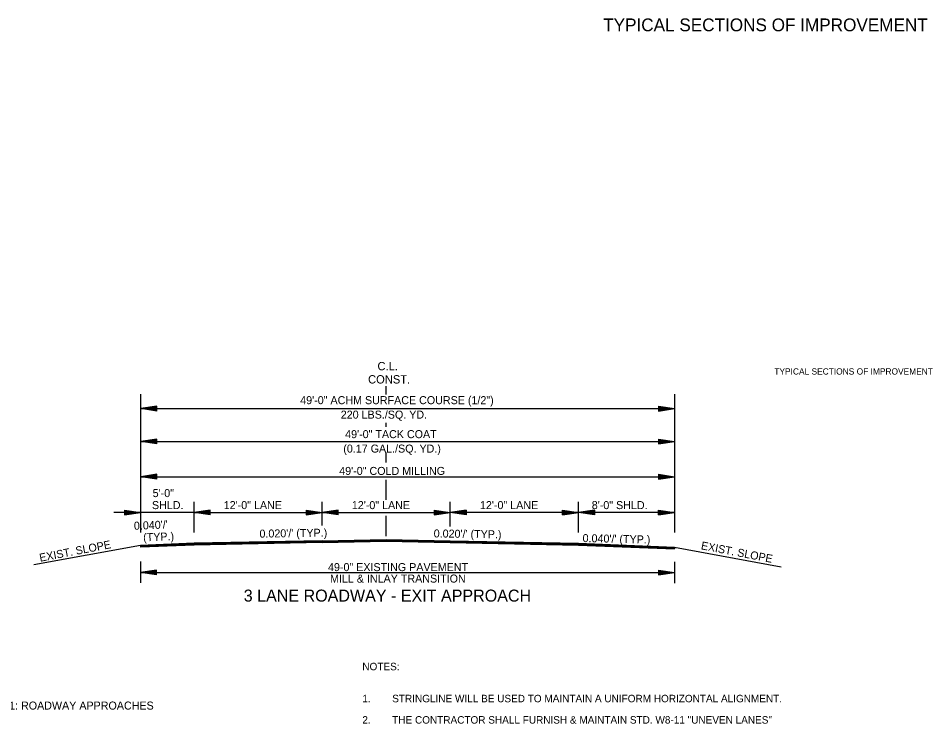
# Model space of a CAD drawing. Extents: x 542112 to 1930787, y -1968972 to 596640.
# Drawn here: x 544899 to 545755, y -1948990 to -1948329 of the extents above; entities that cross this region are included whole.
import ezdxf

# ---------------------------------------------------------------- set-up
doc = ezdxf.new("R2010")
doc.units = 0
for name, color, linetype in [('R_Border', 7, 'Continuous'), ('R_Border Notes', 7, 'Continuous'), ('R_Border Prem', 7, 'Continuous'), ('R_Draft', 7, 'Continuous')]:
    doc.layers.add(name, color=color, linetype=linetype)

msp = doc.modelspace()

# ---------------------------------------------------------------- linework, layer by layer
at = {"layer": 'R_Draft'}
for p, q in [((545243.3, -1948681.18), (545243.3, -1948673.33)), ((545013.3, -1948680.82), (545013.3, -1948810.28)), ((545513.3, -1948680.82), (545513.3, -1948810.28)), ((545028.42, -1948692.04), (545013.42, -1948694.29)), ((545028.42, -1948692.41), (545015.93, -1948694.29)), ((545028.42, -1948696.54), (545028.42, -1948692.04)), ((545498.3, -1948692.04), (545513.3, -1948694.29)), ((545498.3, -1948692.04), (545498.3, -1948696.54)), ((545498.3, -1948692.41), (545510.79, -1948694.29)), ((545013.3, -1948694.29), (545513.3, -1948694.29)), ((545028.42, -1948696.54), (545013.42, -1948694.29)), ((545028.42, -1948696.16), (545015.93, -1948694.29)), ((545028.42, -1948692.79), (545018.51, -1948694.29)), ((545028.42, -1948695.78), (545018.51, -1948694.29)), ((545028.42, -1948693.17), (545021.01, -1948694.29)), ((545028.42, -1948695.4), (545021.01, -1948694.29)), ((545028.42, -1948693.55), (545023.55, -1948694.29)), ((545028.42, -1948695.01), (545023.55, -1948694.29)), ((545028.42, -1948693.93), (545026.05, -1948694.29)), ((545028.42, -1948694.64), (545026.05, -1948694.29)), ((545498.3, -1948692.79), (545508.21, -1948694.29)), ((545498.3, -1948693.17), (545505.72, -1948694.29)), ((545498.3, -1948693.56), (545503.17, -1948694.29)), ((545498.3, -1948693.93), (545500.67, -1948694.29)), ((545498.3, -1948696.54), (545513.3, -1948694.29)), ((545498.3, -1948695.02), (545503.17, -1948694.29)), ((545498.3, -1948695.78), (545508.21, -1948694.29)), ((545498.3, -1948696.16), (545510.79, -1948694.29)), ((545498.3, -1948695.4), (545505.72, -1948694.29)), ((545498.3, -1948694.64), (545500.67, -1948694.29)), ((545243.3, -1948711.31), (545243.3, -1948707.64)), ((545013.3, -1948725.16), (545513.3, -1948725.16)), ((545028.42, -1948722.91), (545013.42, -1948725.16)), ((545028.42, -1948727.41), (545013.42, -1948725.16)), ((545028.42, -1948723.28), (545015.93, -1948725.16)), ((545028.42, -1948727.03), (545015.93, -1948725.16)), ((545028.42, -1948723.66), (545018.51, -1948725.16)), ((545028.42, -1948726.65), (545018.51, -1948725.16)), ((545028.42, -1948724.04), (545021.01, -1948725.16)), ((545028.42, -1948726.27), (545021.01, -1948725.16)), ((545028.42, -1948724.42), (545023.55, -1948725.16)), ((545028.42, -1948725.88), (545023.55, -1948725.16)), ((545028.42, -1948724.8), (545026.05, -1948725.16)), ((545028.42, -1948725.51), (545026.05, -1948725.16)), ((545028.42, -1948727.41), (545028.42, -1948722.91)), ((545498.3, -1948722.91), (545513.3, -1948725.16)), ((545498.3, -1948722.91), (545498.3, -1948727.41)), ((545498.3, -1948723.28), (545510.79, -1948725.16)), ((545498.3, -1948723.66), (545508.21, -1948725.16)), ((545498.3, -1948724.04), (545505.72, -1948725.16)), ((545498.3, -1948724.43), (545503.17, -1948725.16)), ((545498.3, -1948724.8), (545500.67, -1948725.16)), ((545498.3, -1948727.41), (545513.3, -1948725.16)), ((545498.3, -1948725.89), (545503.17, -1948725.16)), ((545498.3, -1948726.65), (545508.21, -1948725.16)), ((545498.3, -1948727.03), (545510.79, -1948725.16)), ((545498.3, -1948726.27), (545505.72, -1948725.16)), ((545498.3, -1948725.51), (545500.67, -1948725.16)), ((545243.3, -1948744.67), (545243.3, -1948735.37)), ((545013.3, -1948758.09), (545513.3, -1948758.09)), ((545028.42, -1948755.84), (545013.42, -1948758.09)), ((545028.42, -1948760.34), (545013.42, -1948758.09)), ((545028.42, -1948756.21), (545015.93, -1948758.09)), ((545028.42, -1948759.96), (545015.93, -1948758.09)), ((545028.42, -1948756.59), (545018.51, -1948758.09)), ((545028.42, -1948759.58), (545018.51, -1948758.09)), ((545028.42, -1948756.97), (545021.01, -1948758.09)), ((545028.42, -1948759.2), (545021.01, -1948758.09)), ((545028.42, -1948757.35), (545023.55, -1948758.09)), ((545028.42, -1948758.81), (545023.55, -1948758.09)), ((545028.42, -1948757.73), (545026.05, -1948758.09)), ((545028.42, -1948758.44), (545026.05, -1948758.09)), ((545028.42, -1948760.34), (545028.42, -1948755.84)), ((545243.3, -1948779.61), (545243.3, -1948760.91)), ((545498.3, -1948755.84), (545513.3, -1948758.09)), ((545498.3, -1948755.84), (545498.3, -1948760.34)), ((545498.3, -1948756.21), (545510.79, -1948758.09)), ((545498.3, -1948756.59), (545508.21, -1948758.09)), ((545498.3, -1948756.97), (545505.72, -1948758.09)), ((545498.3, -1948757.36), (545503.17, -1948758.09)), ((545498.3, -1948757.73), (545500.67, -1948758.09)), ((545498.3, -1948760.34), (545513.3, -1948758.09)), ((545498.3, -1948758.82), (545503.17, -1948758.09)), ((545498.3, -1948759.58), (545508.21, -1948758.09)), ((545498.3, -1948759.96), (545510.79, -1948758.09)), ((545498.3, -1948759.2), (545505.72, -1948758.09)), ((545498.3, -1948758.44), (545500.67, -1948758.09)), ((545063.3, -1948810.28), (545063.3, -1948781.73)), ((545183.3, -1948803.7), (545183.3, -1948781.73)), ((545303.3, -1948804.69), (545303.3, -1948781.73)), ((545423.3, -1948810.28), (545423.3, -1948781.73)), ((545013.3, -1948791.62), (544988.3, -1948791.62)), ((544998.3, -1948789.37), (545013.3, -1948791.62)), ((544998.3, -1948789.37), (544998.3, -1948793.87)), ((544998.3, -1948789.75), (545010.79, -1948791.62)), ((544998.3, -1948790.13), (545008.21, -1948791.62)), ((544998.3, -1948790.51), (545005.72, -1948791.62)), ((544998.3, -1948790.9), (545003.17, -1948791.62)), ((544998.3, -1948791.27), (545000.67, -1948791.62)), ((544998.3, -1948793.87), (545013.3, -1948791.62)), ((544998.3, -1948792.36), (545003.17, -1948791.62)), ((544998.3, -1948793.12), (545008.21, -1948791.62)), ((544998.3, -1948793.5), (545010.79, -1948791.62)), ((544998.3, -1948792.74), (545005.72, -1948791.62)), ((544998.3, -1948791.98), (545000.67, -1948791.62)), ((545063.3, -1948791.62), (545013.3, -1948791.62)), ((545078.3, -1948789.37), (545063.3, -1948791.62)), ((545063.3, -1948791.62), (545183.3, -1948791.62)), ((545078.3, -1948793.87), (545063.3, -1948791.62)), ((545078.3, -1948789.75), (545065.8, -1948791.62)), ((545078.3, -1948793.5), (545065.8, -1948791.62)), ((545078.3, -1948790.13), (545068.38, -1948791.62)), ((545078.3, -1948793.12), (545068.38, -1948791.62)), ((545078.3, -1948790.51), (545070.88, -1948791.62)), ((545078.3, -1948792.74), (545070.88, -1948791.62)), ((545078.3, -1948790.89), (545073.42, -1948791.62)), ((545078.3, -1948792.35), (545073.42, -1948791.62)), ((545078.3, -1948791.27), (545075.93, -1948791.62)), ((545078.3, -1948791.98), (545075.93, -1948791.62)), ((545078.3, -1948793.87), (545078.3, -1948789.37)), ((545168.3, -1948789.37), (545183.3, -1948791.62)), ((545168.3, -1948789.37), (545168.3, -1948793.87)), ((545168.3, -1948789.75), (545180.79, -1948791.62)), ((545168.3, -1948790.13), (545178.21, -1948791.62)), ((545168.3, -1948790.51), (545175.72, -1948791.62)), ((545168.3, -1948790.9), (545173.17, -1948791.62)), ((545168.3, -1948791.27), (545170.67, -1948791.62)), ((545168.3, -1948793.87), (545183.3, -1948791.62)), ((545168.3, -1948792.36), (545173.17, -1948791.62)), ((545168.3, -1948793.12), (545178.21, -1948791.62)), ((545168.3, -1948793.5), (545180.79, -1948791.62)), ((545168.3, -1948792.74), (545175.72, -1948791.62)), ((545168.3, -1948791.98), (545170.67, -1948791.62)), ((545198.3, -1948789.37), (545183.3, -1948791.62)), ((545183.3, -1948791.62), (545303.3, -1948791.62)), ((545198.3, -1948793.87), (545183.3, -1948791.62)), ((545198.3, -1948789.75), (545185.8, -1948791.62)), ((545198.3, -1948793.5), (545185.8, -1948791.62)), ((545198.3, -1948790.13), (545188.38, -1948791.62)), ((545198.3, -1948793.12), (545188.38, -1948791.62)), ((545198.3, -1948790.51), (545190.88, -1948791.62)), ((545198.3, -1948792.74), (545190.88, -1948791.62)), ((545198.3, -1948790.89), (545193.42, -1948791.62)), ((545198.3, -1948792.35), (545193.42, -1948791.62)), ((545198.3, -1948791.27), (545195.93, -1948791.62)), ((545198.3, -1948791.98), (545195.93, -1948791.62)), ((545198.3, -1948793.87), (545198.3, -1948789.37)), ((545243.3, -1948813.68), (545243.3, -1948794.74)), ((545288.3, -1948789.37), (545303.3, -1948791.62)), ((545288.3, -1948789.37), (545288.3, -1948793.87)), ((545288.3, -1948789.75), (545300.79, -1948791.62)), ((545288.3, -1948790.13), (545298.21, -1948791.62)), ((545288.3, -1948790.51), (545295.72, -1948791.62)), ((545288.3, -1948790.9), (545293.17, -1948791.62)), ((545288.3, -1948791.27), (545290.67, -1948791.62)), ((545288.3, -1948793.87), (545303.3, -1948791.62)), ((545288.3, -1948792.36), (545293.17, -1948791.62)), ((545288.3, -1948793.12), (545298.21, -1948791.62)), ((545288.3, -1948793.5), (545300.79, -1948791.62)), ((545288.3, -1948792.74), (545295.72, -1948791.62)), ((545288.3, -1948791.98), (545290.67, -1948791.62)), ((545318.3, -1948789.37), (545303.3, -1948791.62)), ((545423.3, -1948791.62), (545303.3, -1948791.62)), ((545318.3, -1948793.87), (545303.3, -1948791.62)), ((545318.3, -1948789.75), (545305.8, -1948791.62)), ((545318.3, -1948793.5), (545305.8, -1948791.62)), ((545318.3, -1948790.13), (545308.38, -1948791.62)), ((545318.3, -1948793.12), (545308.38, -1948791.62)), ((545318.3, -1948790.51), (545310.88, -1948791.62)), ((545318.3, -1948792.74), (545310.88, -1948791.62)), ((545318.3, -1948790.9), (545313.42, -1948791.62)), ((545318.3, -1948792.36), (545313.42, -1948791.62)), ((545318.3, -1948791.27), (545315.93, -1948791.62)), ((545318.3, -1948791.98), (545315.93, -1948791.62)), ((545318.3, -1948789.37), (545318.3, -1948793.87)), ((545408.3, -1948789.37), (545423.3, -1948791.62)), ((545408.3, -1948793.87), (545408.3, -1948789.37)), ((545408.3, -1948789.75), (545420.79, -1948791.62)), ((545408.3, -1948790.13), (545418.21, -1948791.62)), ((545408.3, -1948790.51), (545415.72, -1948791.62)), ((545408.3, -1948790.89), (545413.17, -1948791.62)), ((545408.3, -1948791.27), (545410.67, -1948791.62)), ((545408.3, -1948793.87), (545423.3, -1948791.62)), ((545408.3, -1948792.35), (545413.17, -1948791.62)), ((545408.3, -1948793.12), (545418.21, -1948791.62)), ((545408.3, -1948793.5), (545420.79, -1948791.62)), ((545408.3, -1948792.74), (545415.72, -1948791.62)), ((545408.3, -1948791.98), (545410.67, -1948791.62)), ((545438.3, -1948789.37), (545423.3, -1948791.62)), ((545513.3, -1948791.62), (545423.3, -1948791.62)), ((545438.3, -1948793.87), (545423.3, -1948791.62)), ((545438.3, -1948789.75), (545425.8, -1948791.62)), ((545438.3, -1948793.5), (545425.8, -1948791.62)), ((545438.3, -1948790.13), (545428.38, -1948791.62)), ((545438.3, -1948793.12), (545428.38, -1948791.62)), ((545438.3, -1948790.51), (545430.88, -1948791.62)), ((545438.3, -1948792.74), (545430.88, -1948791.62)), ((545438.3, -1948790.9), (545433.42, -1948791.62)), ((545438.3, -1948792.36), (545433.42, -1948791.62)), ((545438.3, -1948791.27), (545435.93, -1948791.62)), ((545438.3, -1948791.98), (545435.93, -1948791.62)), ((545438.3, -1948789.37), (545438.3, -1948793.87)), ((545498.3, -1948789.37), (545513.3, -1948791.62)), ((545498.3, -1948793.87), (545498.3, -1948789.37)), ((545498.3, -1948789.75), (545510.79, -1948791.62)), ((545498.3, -1948790.13), (545508.21, -1948791.62)), ((545498.3, -1948790.51), (545505.72, -1948791.62)), ((545498.3, -1948790.89), (545503.17, -1948791.62)), ((545498.3, -1948791.27), (545500.67, -1948791.62)), ((545498.3, -1948793.87), (545513.3, -1948791.62)), ((545498.3, -1948792.35), (545503.17, -1948791.62)), ((545498.3, -1948793.12), (545508.21, -1948791.62)), ((545498.3, -1948793.5), (545510.79, -1948791.62)), ((545498.3, -1948792.74), (545505.72, -1948791.62)), ((545498.3, -1948791.98), (545500.67, -1948791.62)), ((545063.3, -1948820.43), (545013.3, -1948822.43)), ((545063.31, -1948820.73), (545013.3, -1948822.73)), ((545183.3, -1948818.03), (545063.3, -1948820.43)), ((545183.3, -1948818.33), (545063.31, -1948820.73)), ((545183.31, -1948818.63), (545063.32, -1948821.03)), ((545183.32, -1948818.93), (545063.32, -1948821.33)), ((545183.32, -1948819.23), (545063.33, -1948821.63)), ((545183.33, -1948819.53), (545063.34, -1948821.93)), ((545183.33, -1948819.7), (545063.35, -1948822.1)), ((545183.3, -1948818.03), (545243.3, -1948816.83)), ((545183.3, -1948818.33), (545243.3, -1948817.13)), ((545183.31, -1948818.63), (545243.3, -1948817.43)), ((545183.32, -1948818.93), (545243.3, -1948817.73)), ((545183.32, -1948819.23), (545243.3, -1948818.03)), ((545183.33, -1948819.53), (545243.3, -1948818.33)), ((545183.33, -1948819.7), (545243.3, -1948818.5)), ((545243.3, -1948816.83), (545303.3, -1948818.03)), ((545243.3, -1948817.13), (545303.29, -1948818.33)), ((545243.3, -1948817.43), (545303.29, -1948818.63)), ((545243.3, -1948817.73), (545303.28, -1948818.93)), ((545243.3, -1948818.03), (545303.27, -1948819.23)), ((545243.3, -1948818.33), (545303.27, -1948819.53)), ((545243.3, -1948818.5), (545303.26, -1948819.7)), ((545303.26, -1948819.7), (545423.25, -1948822.1)), ((545303.27, -1948819.23), (545423.26, -1948821.63)), ((545303.27, -1948819.53), (545423.25, -1948821.93)), ((545303.28, -1948818.93), (545423.27, -1948821.33)), ((545303.29, -1948818.33), (545423.29, -1948820.73)), ((545303.29, -1948818.63), (545423.28, -1948821.03)), ((545303.3, -1948818.03), (545423.3, -1948820.43)), ((545423.29, -1948820.73), (545513.3, -1948824.33)), ((545423.3, -1948820.43), (545513.3, -1948824.03)), ((545013.3, -1948822.43), (544913.23, -1948840.81)), ((545063.32, -1948821.03), (545013.3, -1948823.03)), ((545063.32, -1948821.33), (545013.3, -1948823.33)), ((545063.33, -1948821.63), (545013.3, -1948823.63)), ((545063.34, -1948821.93), (545013.3, -1948823.93)), ((545063.35, -1948822.1), (545013.3, -1948824.1)), ((545013.3, -1948822.43), (545013.3, -1948824.1)), ((545423.25, -1948821.93), (545513.3, -1948825.53)), ((545423.25, -1948822.1), (545513.3, -1948825.7)), ((545423.26, -1948821.63), (545513.3, -1948825.23)), ((545423.27, -1948821.33), (545513.3, -1948824.93)), ((545423.28, -1948821.03), (545513.3, -1948824.63)), ((545513.3, -1948824.03), (545513.3, -1948825.7)), ((545513.3, -1948824.03), (545613.37, -1948842.41)), ((545013.3, -1948837.64), (545013.3, -1948857.64)), ((545513.3, -1948837.96), (545513.3, -1948857.96)), ((545028.28, -1948845.64), (545013.28, -1948847.89)), ((545028.28, -1948846.01), (545015.79, -1948847.89)), ((545028.28, -1948846.39), (545018.37, -1948847.89)), ((545028.28, -1948850.14), (545028.28, -1948845.64)), ((545498.27, -1948845.64), (545513.27, -1948847.89)), ((545498.27, -1948845.64), (545498.27, -1948850.14)), ((545498.27, -1948846.01), (545510.77, -1948847.89)), ((545498.27, -1948846.39), (545508.19, -1948847.89)), ((545028.28, -1948850.14), (545013.28, -1948847.89)), ((545013.3, -1948847.89), (545513.3, -1948847.89)), ((545028.28, -1948849.76), (545015.79, -1948847.89)), ((545028.28, -1948849.38), (545018.37, -1948847.89)), ((545028.28, -1948846.77), (545020.87, -1948847.89)), ((545028.28, -1948849), (545020.87, -1948847.89)), ((545028.28, -1948847.15), (545023.41, -1948847.89)), ((545028.28, -1948848.61), (545023.41, -1948847.89)), ((545028.28, -1948847.53), (545025.91, -1948847.89)), ((545028.28, -1948848.24), (545025.91, -1948847.89)), ((545498.27, -1948846.77), (545505.69, -1948847.89)), ((545498.27, -1948847.16), (545503.15, -1948847.89)), ((545498.27, -1948847.53), (545500.64, -1948847.89)), ((545498.27, -1948850.14), (545513.27, -1948847.89)), ((545498.27, -1948848.62), (545503.15, -1948847.89)), ((545498.27, -1948849.38), (545508.19, -1948847.89)), ((545498.27, -1948849.76), (545510.77, -1948847.89)), ((545498.27, -1948849), (545505.69, -1948847.89)), ((545498.27, -1948848.24), (545500.64, -1948847.89))]:
    msp.add_line(p, q, dxfattribs=at)

# ---------------------------------------------------------------- texts
at = {"layer": 'R_Border'}
msp.add_text('TYPICAL SECTIONS OF IMPROVEMENT', height=12, rotation=360, dxfattribs=at).set_placement((545446.5, -1948340.71))
at = {"layer": 'R_Border Notes'}
for s, p in [('NOTES: ', (545220.95, -1948939.45)), ('1.', (545220.95, -1948969.45)), ('STRINGLINE WILL BE USED TO MAINTAIN A UNIFORM HORIZONTAL ALIGNMENT.', (545248.95, -1948969.45)), ('2.', (545220.95, -1948989.45)), ('THE CONTRACTOR SHALL FURNISH & MAINTAIN STD. W8-11 "UNEVEN LANES" ', (545248.95, -1948989.45))]:
    msp.add_text(s, height=7, dxfattribs=at).set_placement(p)
at = {"layer": 'R_Border Prem'}
msp.add_text('TYPICAL SECTIONS OF IMPROVEMENT', height=5.862, rotation=360, dxfattribs=at).set_placement((545606.81, -1948662.39))
at = {"layer": 'R_Draft'}
for s, height, p in [('C.L.', 7.8, (545235.11, -1948658.39)), ('CONST.', 7.8, (545226.33, -1948670.76)), ('49\'-0" ACHM SURFACE COURSE (1/2")', 7.5, (545162.76, -1948690.12)), ('220 LBS./SQ. YD. ', 7.5, (545200.74, -1948703.66)), ('49\'-0" TACK COAT', 7.5, (545204.85, -1948721.95)), ('(0.17 GAL./SQ. YD.)', 7.5, (545203.11, -1948735.5)), ('49\'-0" COLD MILLING', 7.5, (545199.3, -1948756.42)), ('5\'-0" ', 7.5, (545024.57, -1948777.2)), ('SHLD.', 7.5, (545023.89, -1948788.45)), ('12\'-0" LANE', 7.5, (545091.11, -1948788.45)), ('12\'-0" LANE', 7.5, (545211.11, -1948788.45)), ('12\'-0" LANE', 7.5, (545331.11, -1948788.45)), ('8\'-0" SHLD.', 7.5, (545435.82, -1948788.45)), ('49-0" EXISTING PAVEMENT', 7.5, (545188.8, -1948846.56)), ('MILL & INLAY TRANSITION', 7.5, (545190.69, -1948857.29)), ('3 LANE ROADWAY - EXIT APPROACH', 11.25, (545109.87, -1948875.13)), ('4 - BR. NO. B5392 - HWY. 71: ROADWAY APPROACHES', 7.5, (544763.05, -1948976.29))]:
    msp.add_text(s, height=height, dxfattribs=at).set_placement(p)
for s, rotation, p in [("  0.040'/'", 2.44797, (545001.59, -1948808.11)), (' (TYP.)', 2.44797, (545013.02, -1948818.88)), ("0.020'/' (TYP.)", 0.87191, (545124.66, -1948815.21)), ("0.020'/' (TYP.)", 359.12809, (545287.74, -1948814.95)), ("0.040'/' (TYP.)", 358.68162, (545427.18, -1948819.31)), ('EXIST. SLOPE', 10.88286, (544919.21, -1948837.83)), ('EXIST. SLOPE', 349.11714, (545537.68, -1948826.02))]:
    msp.add_text(s, height=7.5, rotation=rotation, dxfattribs=at).set_placement(p)

doc.saveas('drawing.dxf')
